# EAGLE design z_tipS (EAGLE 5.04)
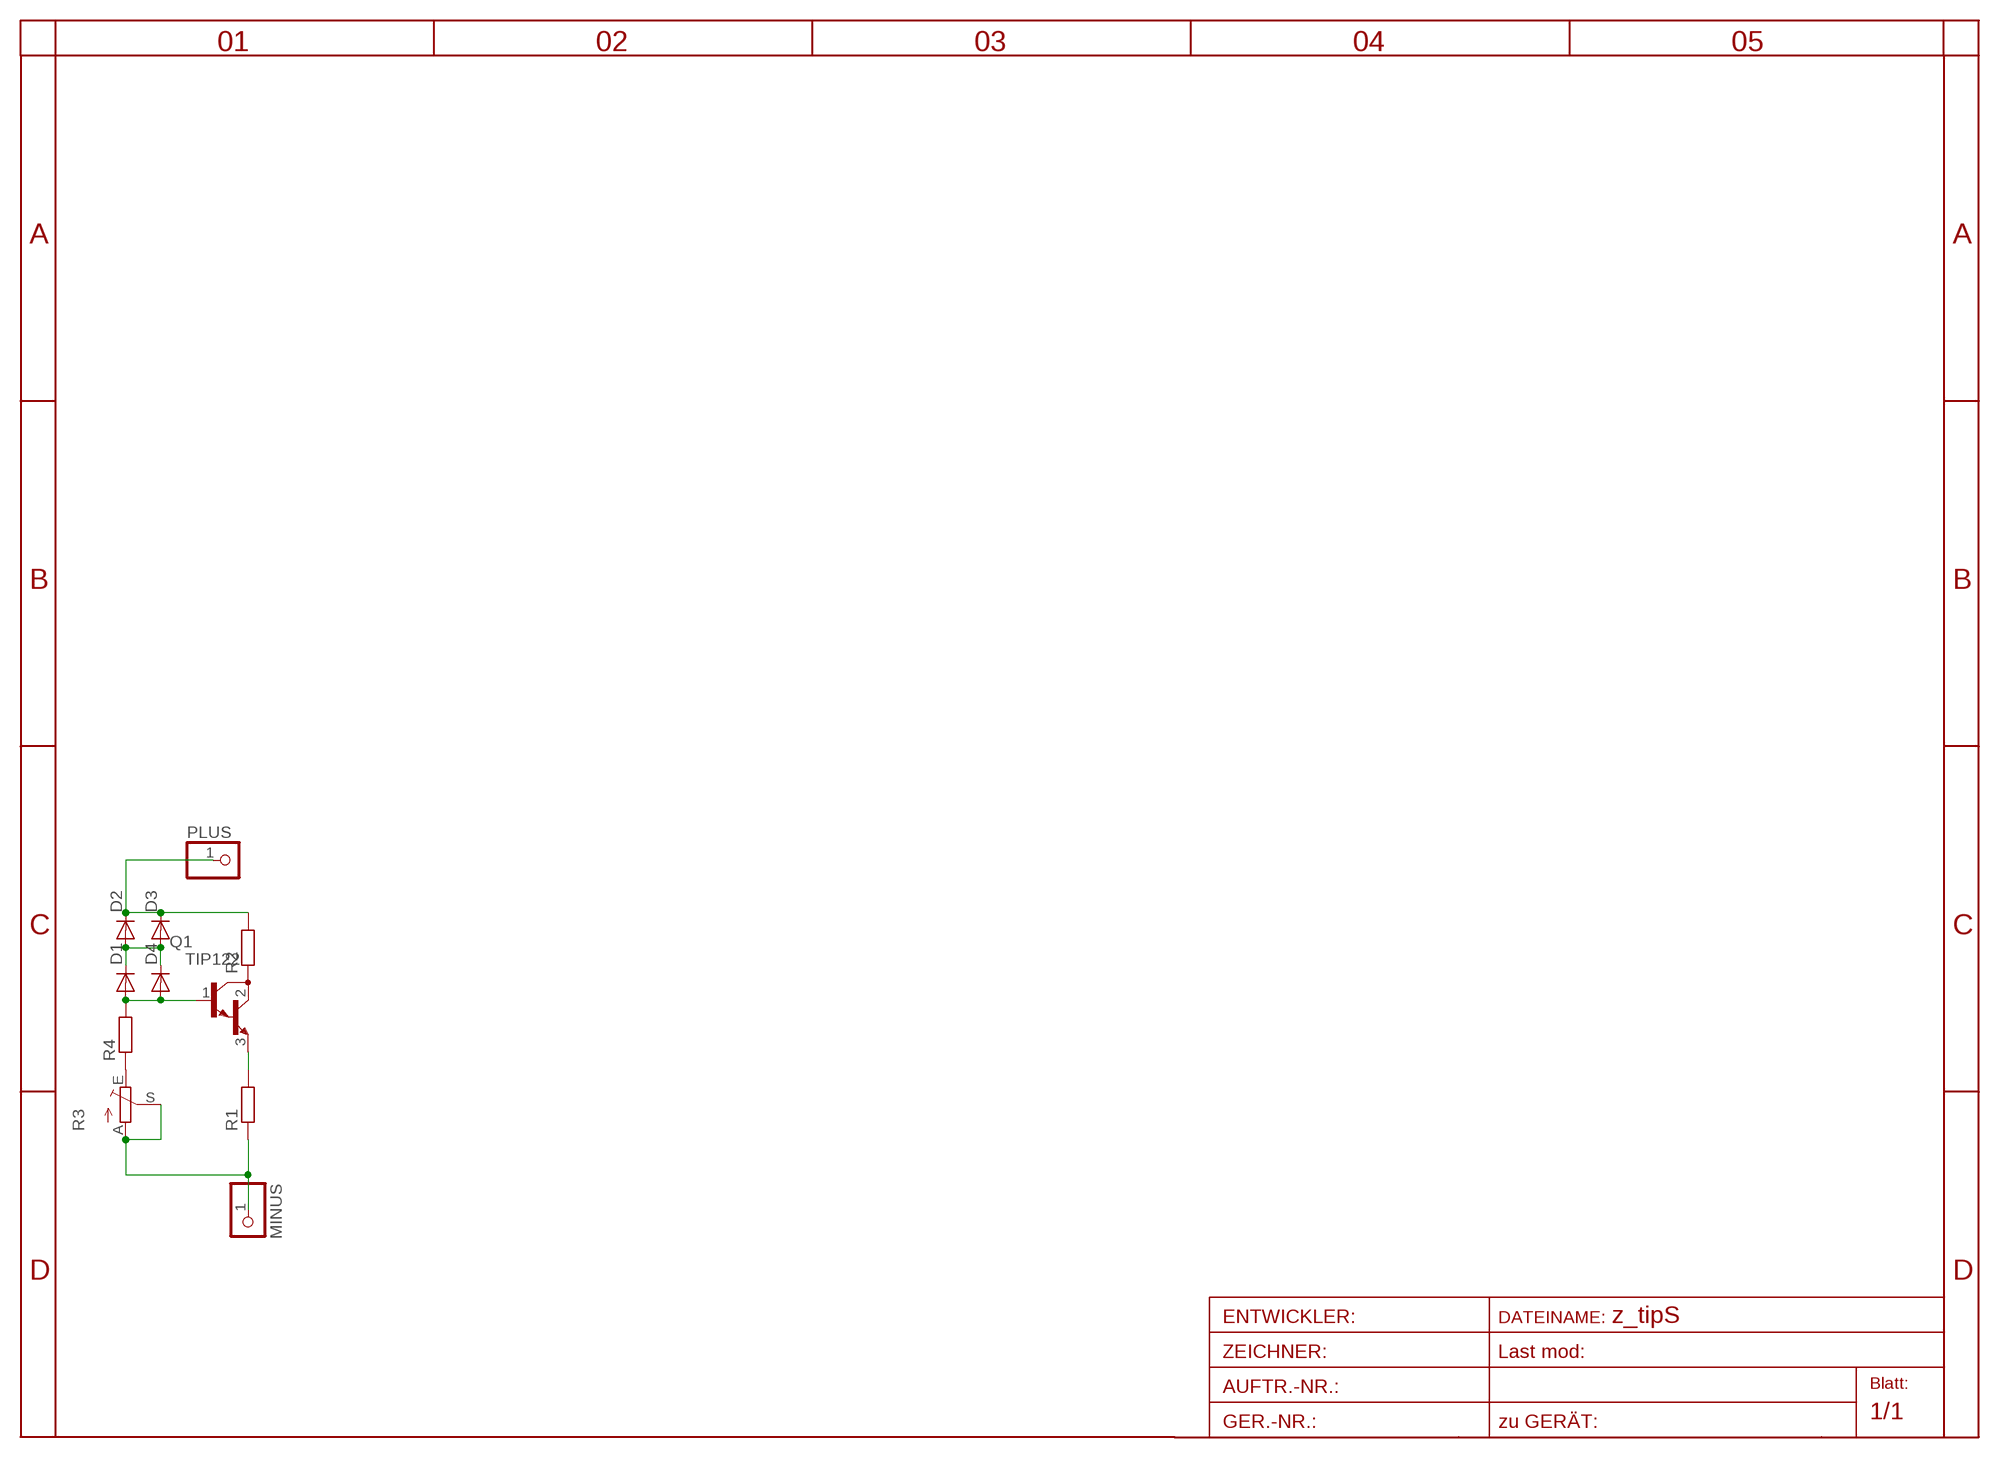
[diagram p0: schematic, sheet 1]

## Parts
D1  DIODE-MINIMELF  [MINIMELF]
D2  DIODE-MINIMELF  [MINIMELF]
D3  DIODE-D-2.5  [D-2.5]
D4  DIODE-D-2.5  [D-2.5]
MINUS  PINHD-1X1  [1X01]
PLUS  PINHD-1X1  [1X01]
Q1  TIP122  [TO220]
R1  R-EU_0411/15  [0411/15]
R2  R-EU_0817/7V  [P0817V]
R3  TRIM_EU-CA6V  [CA6V]
R4  R-EU_R1206  [R1206]

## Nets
C: Q1.2(C) R2.1
E: Q1.3(E) R1.2
MINUS: MINUS.1 R1.1 R3.A R3.S
N$1: D1.A D4.A Q1.1(B) R4.2
N$2: D1.C D2.A D3.A D4.C
N$3: R3.E R4.1
PLUS: D2.C D3.C PLUS.1 R2.2

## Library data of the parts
D1-D4 = diode-1:DIODE-: DIODE
MINUS PLUS = pinhead:PINHD-1X1: PIN HEADER
Q1 = transistor-npn:TIP122*: NPN Darlington Transistor
R1 R2 R4 = rcl:R-EU_: RESISTOR, European symbol
R3 = pot:TRIM_EU-: POTENTIOMETER

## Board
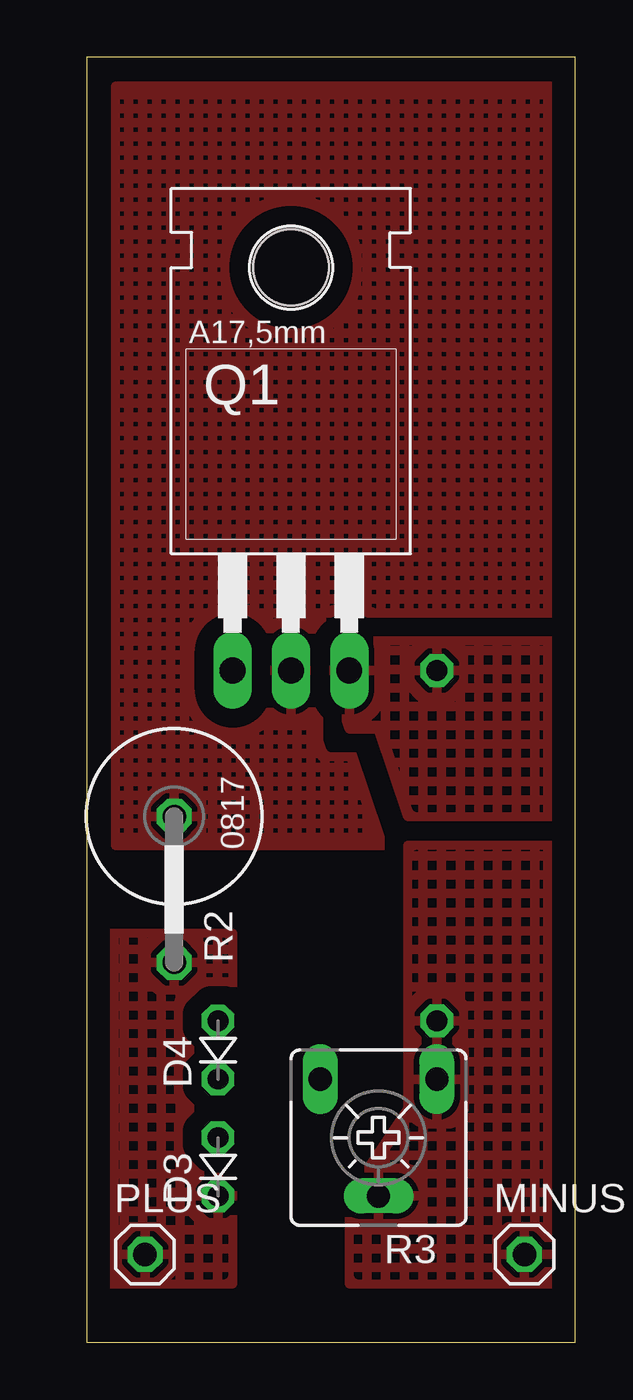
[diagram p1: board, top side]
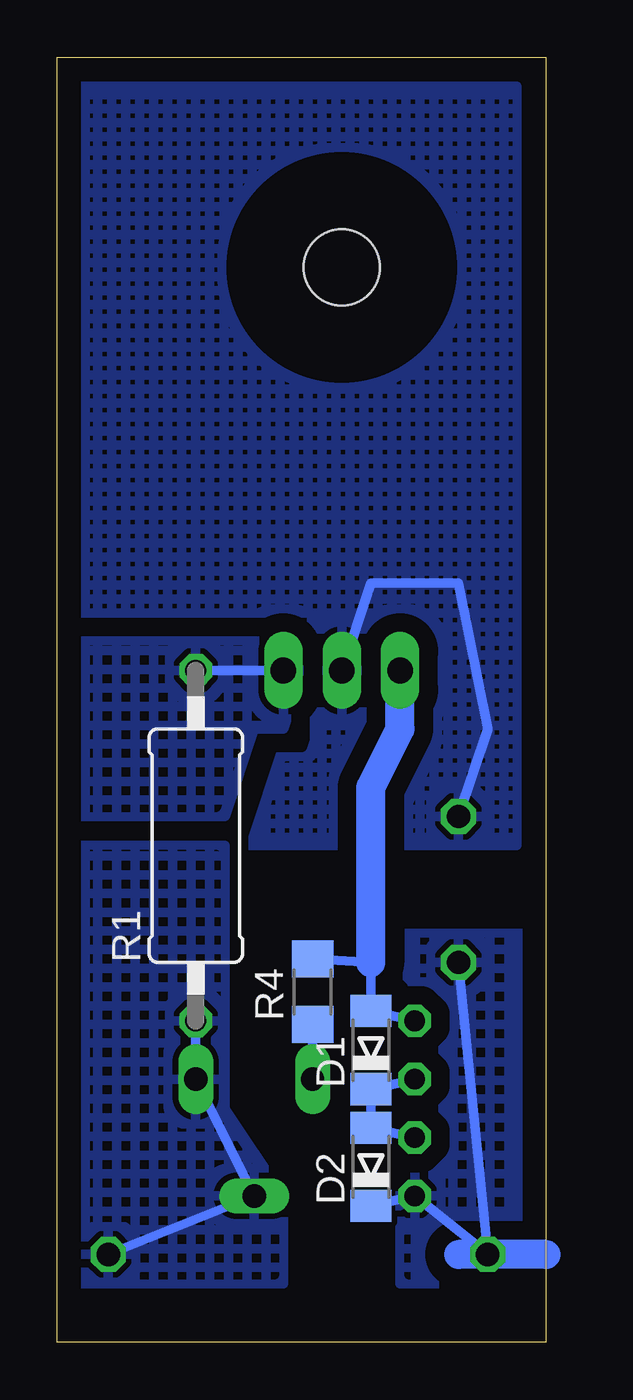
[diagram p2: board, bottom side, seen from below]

Size 21.26 x 55.87 mm. Coordinates in mm from the lower left corner, seen from the top.
Outline: 0,0 21.26,0 21.26,55.87 0,55.87 0,0
Copper layers (1*16): Top 0.035mm / dielectric 1.5mm / Bottom 0.035mm
Design rules "default": minimum track width 10mil, minimum drill 24mil, track to track 8mil, track to pad 8mil, pad to pad 8mil, via to via 8mil, smd to smd 8mil, copper to edge 40mil, drill to drill 8mil, minimum pad ring 10mil, minimum via ring 8mil, stop-mask expansion 4mil, vias tented up to drill 0mil, thermal gap 10mil

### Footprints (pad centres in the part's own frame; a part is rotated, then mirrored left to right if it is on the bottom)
MINIMELF = smd 1.4 x 1.8: A 1.7,0; C -1.7,0
D-2.5 = drill 0.9 octagon: A 1.27,0; C -1.27,0
1X01 = drill 1.016 octagon: 1 0,0
TO220 = drill 1.118 long: 1 -2.54,-6.35; 2 0,-6.35; 3 2.54,-6.35 | hole 3.302: 0,11.176
0411/15 = drill 0.914 octagon: 1 -7.62,0; 2 7.62,0
P0817V = drill 1.016 octagon: 1 -5.08,0; 2 1.27,0
CA6V = drill 1.016 long: A -2.54,-2.54; E 2.54,-2.54; S 0,2.54
R1206 = smd 1.6 x 1.803: 1 -1.422,0; 2 1.422,0

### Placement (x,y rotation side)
D1  7.62,12.7 90 bottom
D2  7.62,7.62 90 bottom
D3  5.71,7.62 90 top
D4  5.71,12.7 90 top
MINUS  19.05,3.81 0 top
PLUS  2.54,3.81 0 top
Q1  8.89,35.56 0 top
R1  15.24,21.59 90 bottom
R2  3.81,17.78 270 top
R3  12.7,8.89 180 top
R4  10.16,15.24 90 bottom

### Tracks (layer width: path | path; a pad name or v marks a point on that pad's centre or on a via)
C
  Bottom 0.406: R2.1 2.54,26.67 3.81,33.02 7.62,33.02 Q1.2
  pour Bottom (isolate 0.813, rank 3, hatched): 20.32,21.59 1.27,21.59 1.27,54.61 20.32,54.61
  pour Top (isolate 0.813, rank 3, hatched): 20.32,21.59 1.27,21.59 1.27,54.61 20.32,54.61
E
  Bottom 0.406: Q1.3 R1.2
  pour Bottom (isolate 0.813, rank 2, hatched): 10.16,30.48 20.32,30.48 20.32,22.86 13.97,22.86 12.7,26.67 11.43,26.67
  pour Top (isolate 0.813, rank 2, hatched): 10.16,30.48 20.32,30.48 20.32,22.86 13.97,22.86 12.7,26.67 11.43,26.67
MINUS
  Bottom 0.406: MINUS.1 R3.S R3.A R1.1
  pour Bottom (isolate 0.813, hatched): 13.97,21.59 20.32,21.59 20.32,2.54 11.43,2.54 11.43,6.35 13.97,10.16
  pour Top (isolate 0.813, hatched): 13.97,21.59 20.32,21.59 20.32,2.54 11.43,2.54 11.43,6.35 13.97,10.16
N$1
  Bottom 0.406: D4.A D1.A 7.62,16.51 R4.2
  Bottom 1.27: 7.62,16.51 7.62,24.13 6.35,26.67 Q1.1
N$2
  Bottom 0.406: D3.A D2.A D1.C D4.C
N$3
  Bottom 0.406: R3.E R4.1
N$5
  Bottom 1.27: 0,3.81 3.81,3.81
PLUS
  Bottom 0.406: R2.2 PLUS.1 D3.C D2.C
  pour Bottom (isolate 0.813, hatched): 0,17.78 6.35,17.78 6.35,2.54 0,2.54
  pour Top (isolate 0.813, hatched): 0,17.78 6.35,17.78 6.35,2.54 0,2.54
